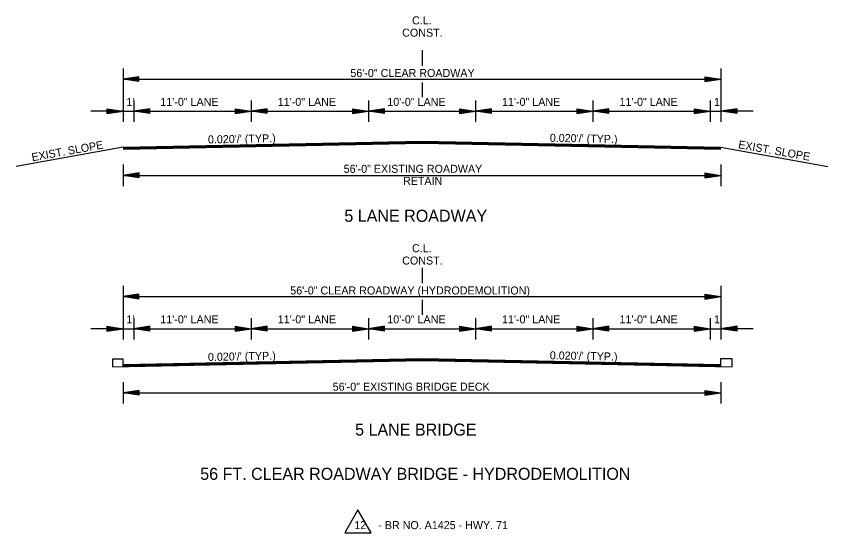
# Model space of a CAD drawing. Extents: x 549600 to 1930787, y -1955432 to 596640.
# Drawn here: x 551242 to 552002, y -1950417 to -1949934 of the extents above; entities that cross this region are included whole.
import ezdxf

# ---------------------------------------------------------------- set-up
doc = ezdxf.new("R2010")
doc.units = 0
doc.layers.add('R_Border', color=7, linetype='Continuous')
doc.layers.add('S_AREA_CALC', color=7, linetype='Continuous')

# ---------------------------------------------------------------- blocks, each defined once
blk = doc.blocks.new('ARROW')
at = {"layer": 'S_AREA_CALC'}
for p, q in [((-2, 0.3), (0, 0)), ((-2, 0.3), (-2, -0.3)), ((-2, 0.25), (-0.334, 0)), ((-2, 0.199), (-0.678, 0)), ((-2, 0.149), (-1.011, 0)), ((-2, 0.097), (-1.35, 0)), ((-2, 0.047), (-1.684, 0)), ((-2, -0.3), (0, 0)), ((-2, -0.098), (-1.35, 0)), ((-2, -0.199), (-0.678, 0)), ((-2, -0.25), (-0.334, 0)), ((-2, -0.149), (-1.011, 0)), ((-2, -0.047), (-1.684, 0))]:
    blk.add_line(p, q, dxfattribs=at)

msp = doc.modelspace()

# ---------------------------------------------------------------- linework, layer by layer
at = {"layer": 'R_Border'}
for p, q in [((551622.02, -1949965.74), (551622.02, -1949980.24)), ((551342.02, -1949982.74), (551342.02, -1950032.74)), ((551902.02, -1949982.74), (551902.02, -1950032.74)), ((551342.02, -1949992.74), (551902.02, -1949992.74)), ((551622.02, -1949995.74), (551622.02, -1950009.74)), ((551352.02, -1950012.74), (551352.02, -1950032.74)), ((551462.02, -1950012.74), (551462.02, -1950032.74)), ((551572.02, -1950012.74), (551572.02, -1950032.74)), ((551672.02, -1950012.74), (551672.02, -1950032.74)), ((551782.02, -1950012.74), (551782.02, -1950032.74)), ((551892.02, -1950012.74), (551892.02, -1950032.74)), ((551342.02, -1950022.74), (551312.02, -1950022.74)), ((551342.02, -1950022.74), (551902.02, -1950022.74)), ((551932.02, -1950022.74), (551902.02, -1950022.74)), ((551342.02, -1950056.34), (551242.02, -1950074.34)), ((551902.02, -1950056.34), (552002.02, -1950074.34)), ((551342.02, -1950072.74), (551342.02, -1950092.74)), ((551902.02, -1950072.74), (551902.02, -1950092.74)), ((551342.02, -1950082.74), (551902.02, -1950082.74)), ((551622.02, -1950169.2), (551622.02, -1950183.7)), ((551342.02, -1950186.2), (551342.02, -1950236.2)), ((551902.02, -1950186.2), (551902.02, -1950236.2)), ((551342.02, -1950196.2), (551902.02, -1950196.2)), ((551622.02, -1950199.2), (551622.02, -1950213.2)), ((551352.02, -1950216.2), (551352.02, -1950236.2)), ((551462.02, -1950216.2), (551462.02, -1950236.2)), ((551572.02, -1950216.2), (551572.02, -1950236.2)), ((551672.02, -1950216.2), (551672.02, -1950236.2)), ((551782.02, -1950216.2), (551782.02, -1950236.2)), ((551892.02, -1950216.2), (551892.02, -1950236.2)), ((551342.02, -1950226.2), (551312.02, -1950226.2)), ((551342.02, -1950226.2), (551902.02, -1950226.2)), ((551932.02, -1950226.2), (551902.02, -1950226.2)), ((551342.02, -1950276.2), (551342.02, -1950296.2)), ((551902.02, -1950276.2), (551902.02, -1950296.2)), ((551342.02, -1950286.2), (551902.02, -1950286.2)), ((551549.68, -1950417.09), (551574.47, -1950417.09))]:
    msp.add_line(p, q, dxfattribs=at)
for points in [[(551342.02, -1950056.34), (551622.02, -1950050.74), (551902.02, -1950056.34)], [(551342.02, -1950056.64), (551622.02, -1950051.04), (551902.02, -1950056.64)], [(551342.02, -1950056.94), (551622.02, -1950051.34), (551902.02, -1950056.94)], [(551342.02, -1950057.24), (551622.02, -1950051.64), (551902.02, -1950057.24)], [(551342.02, -1950057.54), (551622.02, -1950051.94), (551902.02, -1950057.54)], [(551342.02, -1950057.84), (551622.02, -1950052.24), (551902.02, -1950057.84)], [(551342.02, -1950058.14), (551622.02, -1950052.54), (551902.02, -1950058.14)], [(551342.02, -1950261.3), (551342.02, -1950254.8), (551332.02, -1950254.8), (551332.02, -1950261.8)], [(551332.02, -1950261.8), (551622.02, -1950256), (551912.02, -1950261.8)], [(551342.02, -1950259.8), (551622.02, -1950254.2), (551902.02, -1950259.8)], [(551342.02, -1950260.1), (551622.02, -1950254.5), (551902.02, -1950260.1)], [(551342.02, -1950260.4), (551622.02, -1950254.8), (551902.02, -1950260.4)], [(551342.02, -1950260.7), (551622.02, -1950255.1), (551902.02, -1950260.7)], [(551342.02, -1950261), (551622.02, -1950255.4), (551902.02, -1950261)], [(551342.02, -1950261.3), (551622.02, -1950255.7), (551902.02, -1950261.3)], [(551902.02, -1950261.3), (551902.02, -1950254.1), (551912.02, -1950254.1), (551912.02, -1950261.8)], [(551574.47, -1950417.09), (551562.07, -1950395.62), (551549.68, -1950417.09)]]:
    msp.add_lwpolyline(points, dxfattribs=at)

# ---------------------------------------------------------------- block references
at = {"layer": 'R_Border', "xscale": 7.5, "yscale": 7.5, "rotation": 180}
for p in [(551341.98, -1949992.73), (551352.02, -1950022.74), (551462.02, -1950022.74), (551572.02, -1950022.74), (551672.02, -1950022.74), (551782.02, -1950022.74), (551902.02, -1950022.74), (551342.02, -1950082.74), (551341.98, -1950196.19), (551352.02, -1950226.2), (551462.02, -1950226.2), (551572.02, -1950226.2), (551672.02, -1950226.2), (551782.02, -1950226.2), (551902.02, -1950226.2), (551342.02, -1950286.2)]:
    msp.add_blockref('ARROW', p, dxfattribs=at)
at = {"layer": 'R_Border', "xscale": 7.5, "yscale": 7.5}
for p in [(551902.02, -1949992.74), (551342.02, -1950022.74), (551462.02, -1950022.74), (551572.02, -1950022.74), (551672.02, -1950022.74), (551782.02, -1950022.74), (551892.02, -1950022.74), (551902.02, -1950082.74), (551902.02, -1950196.2), (551342.02, -1950226.2), (551462.02, -1950226.2), (551572.02, -1950226.2), (551672.02, -1950226.2), (551782.02, -1950226.2), (551892.02, -1950226.2), (551902.02, -1950286.2)]:
    msp.add_blockref('ARROW', p, dxfattribs=at)

# ---------------------------------------------------------------- texts
at = {"layer": 'R_Border'}
for s, height, p in [('C.L.', 7.5, (551612.69, -1949941.51)), ('CONST.', 7.5, (551603.47, -1949953.01)), ('56\'-0" CLEAR ROADWAY', 7.5, (551554.93, -1949990.74)), ("1'", 7.5, (551345.19, -1950017.74)), ('11\'-0" LANE', 7.5, (551376.96, -1950017.74)), ('11\'-0" LANE', 7.5, (551486.96, -1950017.74)), ('10\'-0" LANE', 7.5, (551589.54, -1950017.74)), ('11\'-0" LANE', 7.5, (551696.96, -1950017.74)), ('11\'-0" LANE', 7.5, (551806.96, -1950017.74)), ("1'", 7.5, (551895.51, -1950017.74)), ('56\'-0" EXISTING ROADWAY', 7.5, (551548.67, -1950080.38)), ('RETAIN', 7.5, (551604.21, -1950091.63)), ('5 LANE ROADWAY', 11.25, (551549.29, -1950126.2)), ('C.L.', 7.5, (551612.69, -1950154.7)), ('CONST.', 7.5, (551603.47, -1950166.2)), ('56\'-0" CLEAR ROADWAY (HYDRODEMOLITION)', 7.5, (551498.65, -1950194.2)), ("1'", 7.5, (551345.19, -1950221.2)), ('11\'-0" LANE', 7.5, (551376.96, -1950221.2)), ('11\'-0" LANE', 7.5, (551486.96, -1950221.2)), ('10\'-0" LANE', 7.5, (551589.54, -1950221.2)), ('11\'-0" LANE', 7.5, (551696.96, -1950221.2)), ('11\'-0" LANE', 7.5, (551806.96, -1950221.2)), ("1'", 7.5, (551895.51, -1950221.2)), ('56\'-0" EXISTING BRIDGE DECK', 7.5, (551538.4, -1950284.2)), ('5 LANE BRIDGE', 11.25, (551559.39, -1950326.2)), ('56 FT. CLEAR ROADWAY BRIDGE - HYDRODEMOLITION', 11.25, (551414.33, -1950367.6)), ('12', 7.5, (551558.71, -1950413.68)), ('- BR NO. A1425 - HWY. 71', 7.5, (551581.07, -1950413.68))]:
    msp.add_text(s, height=height, dxfattribs=at).set_placement(p)
for s, rotation, p in [("0.020'/' (TYP.)", 1.1458, (551421.63, -1950052.95)), ("0.020'/' (TYP.)", 358.8542, (551741.63, -1950051.33)), ('EXIST. SLOPE', 10.204, (551257.09, -1950069.63)), ('EXIST. SLOPE', 349.98872, (551917.76, -1950057.29)), ("0.020'/' (TYP.)", 1.1458, (551421.63, -1950256.41)), ("0.020'/' (TYP.)", 358.8542, (551741.63, -1950254.79))]:
    msp.add_text(s, height=7.5, rotation=rotation, dxfattribs=at).set_placement(p)

doc.saveas('drawing.dxf')
